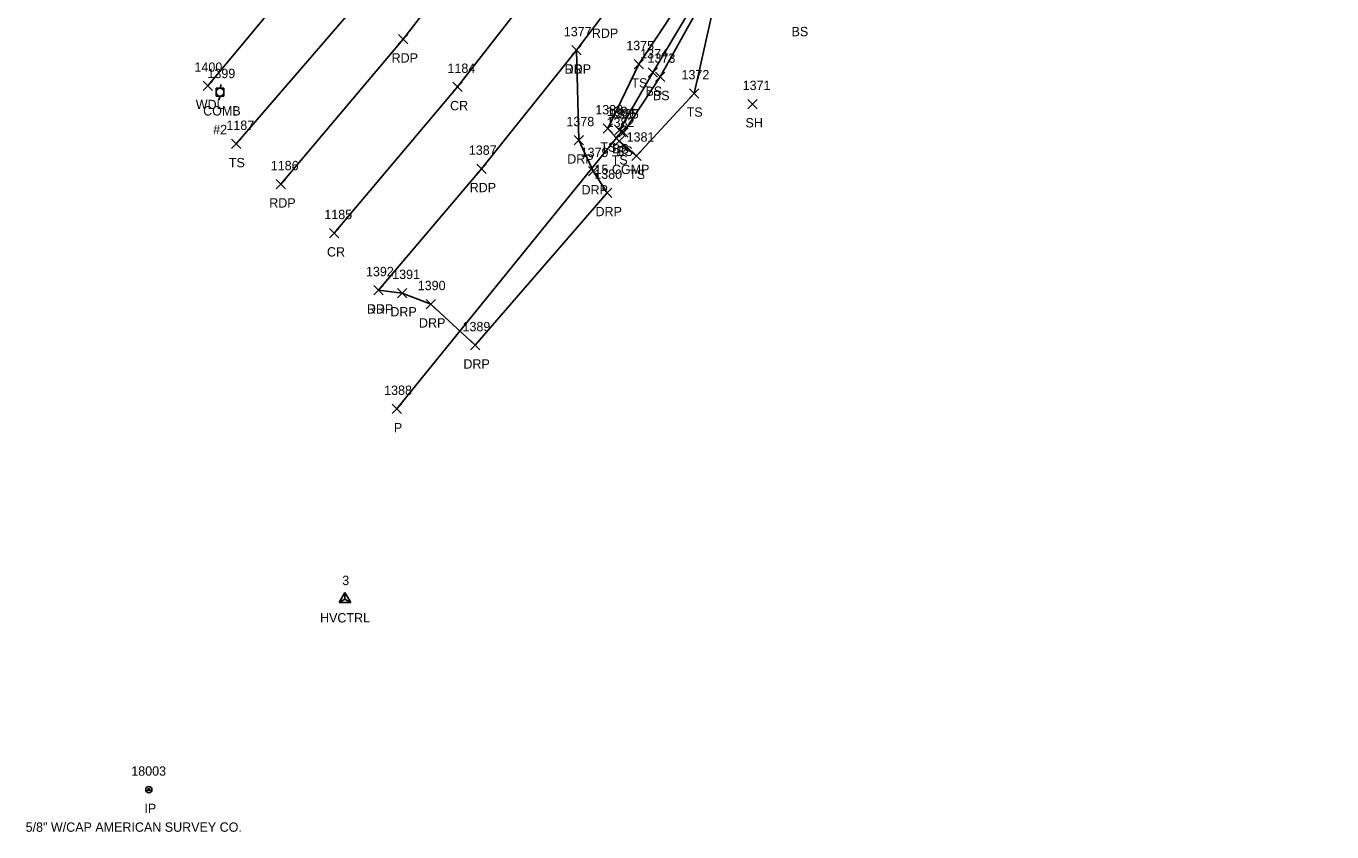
# Model space of a CAD drawing. Extents: x 1599840 to 1601211, y 518904 to 521989.
# Drawn here: x 1600676.4 to 1600955.8, y 521015.9 to 521188.3 of the extents above; entities that cross this region are included whole.
import ezdxf

# ---------------------------------------------------------------- set-up
doc = ezdxf.new("R2010")
doc.units = 0
for name, color, linetype in [('C_A', 7, 'Continuous'), ('C_I', 7, 'Continuous'), ('CPSM', 7, 'Continuous'), ('D_A', 7, 'Continuous'), ('D_C', 7, 'Continuous'), ('D_I', 7, 'Continuous'), ('D_TIC', 7, 'Continuous'), ('DCP', 7, 'Continuous'), ('L_A', 7, 'Continuous'), ('L_I', 7, 'Continuous'), ('L_TIC', 7, 'Continuous'), ('LAWA', 7, 'Continuous'), ('LELB', 7, 'Continuous'), ('M_A', 7, 'Continuous'), ('M_C', 7, 'Continuous'), ('M_I', 7, 'Continuous'), ('MPIR', 7, 'Continuous'), ('P_A', 7, 'Continuous'), ('P_I', 7, 'Continuous'), ('P_TIC', 7, 'Continuous'), ('PET', 7, 'Continuous'), ('PRC', 7, 'Continuous'), ('R_A', 7, 'Continuous'), ('R_I', 7, 'Continuous'), ('R_TIC', 7, 'Continuous'), ('RDP', 7, 'Continuous'), ('U_A', 7, 'Continuous'), ('U_C', 7, 'Continuous'), ('U_I', 7, 'Continuous'), ('UP', 7, 'Continuous')]:
    doc.layers.add(name, color=color, linetype=linetype)

msp = doc.modelspace()

# ---------------------------------------------------------------- linework, layer by layer
at = {"layer": 'CPSM'}
for p, q in [((1600743.33, 521064.98), (1600744.58, 521067.14)), ((1600743.33, 521064.98), (1600744.58, 521065.7)), ((1600745.83, 521064.98), (1600744.58, 521067.14)), ((1600744.58, 521065.7), (1600744.58, 521067.14)), ((1600744.58, 521065.7), (1600744.58, 521065.7)), ((1600744.58, 521065.7), (1600745.83, 521064.98)), ((1600743.33, 521064.98), (1600745.83, 521064.98))]:
    msp.add_line(p, q, dxfattribs=at)
at = {"layer": 'D_TIC'}
for points in [[(1600802.71, 521164.67), (1600804.71, 521166.67)], [(1600804.71, 521164.67), (1600802.71, 521166.67)], [(1600754.68, 521105.4), (1600756.68, 521107.4)], [(1600756.68, 521105.4), (1600754.68, 521107.4)]]:
    msp.add_lwpolyline(points, dxfattribs=at)
at = {"layer": 'DCP'}
msp.add_lwpolyline([(1600803.71, 521165.67), (1600755.68, 521106.4)], dxfattribs=at)
at = {"layer": 'L_TIC'}
for points in [[(1600806.49, 521179.18), (1600808.49, 521181.18)], [(1600808.49, 521179.18), (1600806.49, 521181.18)], [(1600809.47, 521177.41), (1600811.47, 521179.41)], [(1600811.47, 521177.41), (1600809.47, 521179.41)], [(1600811.05, 521176.48), (1600813.05, 521178.48)], [(1600813.05, 521176.48), (1600811.05, 521178.48)], [(1600714.26, 521174.56), (1600716.26, 521176.56)], [(1600716.26, 521174.56), (1600714.26, 521176.56)], [(1600818.31, 521172.94), (1600820.31, 521174.94)], [(1600820.31, 521172.94), (1600818.31, 521174.94)], [(1600830.82, 521170.65), (1600832.82, 521172.65)], [(1600832.82, 521170.65), (1600830.82, 521172.65)], [(1600799.87, 521165.44), (1600801.87, 521167.44)], [(1600801.87, 521165.44), (1600799.87, 521167.44)], [(1600799.87, 521165.44), (1600801.87, 521167.44)], [(1600801.87, 521165.44), (1600799.87, 521167.44)], [(1600802.33, 521165.07), (1600804.33, 521167.07)], [(1600804.33, 521165.07), (1600802.33, 521167.07)], [(1600803.2, 521164.56), (1600805.2, 521166.56)], [(1600805.2, 521164.56), (1600803.2, 521166.56)], [(1600803.2, 521164.56), (1600805.2, 521166.56)], [(1600805.2, 521164.56), (1600803.2, 521166.56)], [(1600720.35, 521162.12), (1600722.35, 521164.12)], [(1600722.35, 521162.12), (1600720.35, 521164.12)], [(1600802.28, 521162.71), (1600804.28, 521164.71)], [(1600804.28, 521162.71), (1600802.28, 521164.71)], [(1600806, 521159.6), (1600808, 521161.6)], [(1600808, 521159.6), (1600806, 521161.6)]]:
    msp.add_lwpolyline(points, dxfattribs=at)
at = {"layer": 'LAWA'}
msp.add_lwpolyline([(1600715.26, 521175.56), (1600743.61, 521209.67), (1600755.16, 521229.87), (1600759.58, 521247.63)], dxfattribs=at)
at = {"layer": 'LELB'}
for points in [[(1600833.08, 521322.84), (1600827.14, 521306.56), (1600810.92, 521276.32), (1600800.69, 521262.52), (1600794.58, 521254.04), (1600785.73, 521239.52), (1600767.25, 521213.82), (1600747.49, 521193.49), (1600721.35, 521163.12)], [(1600856.57, 521262.56), (1600841.46, 521241.68), (1600830.35, 521222.88), (1600827.01, 521208.86), (1600821.28, 521196.5), (1600810.47, 521178.41), (1600803.33, 521166.07), (1600804.2, 521165.56)], [(1600828.05, 521208.69), (1600822.34, 521195.97), (1600812.05, 521177.48), (1600804.2, 521165.56)], [(1600819.4, 521198.14), (1600807.49, 521180.18), (1600800.87, 521166.44)], [(1600824.04, 521195.05), (1600819.31, 521173.94), (1600807, 521160.6), (1600803.28, 521163.71), (1600800.87, 521166.44)]]:
    msp.add_lwpolyline(points, dxfattribs=at)
at = {"layer": 'MPIR'}
msp.add_lwpolyline([(1600702.63, 521025.25), (1600702.34, 521024.75), (1600702.92, 521024.75)], close=True, dxfattribs=at)
msp.add_circle((1600702.63, 521024.91), 0.667, dxfattribs=at)
at = {"layer": 'P_TIC'}
for points in [[(1600756.09, 521184.54), (1600758.09, 521186.54)], [(1600758.09, 521184.54), (1600756.09, 521186.54)], [(1600793.12, 521182.15), (1600795.12, 521184.15)], [(1600795.12, 521182.15), (1600793.12, 521184.15)], [(1600767.67, 521174.32), (1600769.67, 521176.32)], [(1600769.67, 521174.32), (1600767.67, 521176.32)], [(1600772.8, 521156.79), (1600774.8, 521158.79)], [(1600774.8, 521156.79), (1600772.8, 521158.79)], [(1600729.91, 521153.49), (1600731.91, 521155.49)], [(1600731.91, 521153.49), (1600729.91, 521155.49)], [(1600741.32, 521143.02), (1600743.32, 521145.02)], [(1600743.32, 521143.02), (1600741.32, 521145.02)], [(1600750.79, 521130.81), (1600752.79, 521132.81)], [(1600752.79, 521130.81), (1600750.79, 521132.81)]]:
    msp.add_lwpolyline(points, dxfattribs=at)
at = {"layer": 'PET'}
for points in [[(1600925.83, 521507.52), (1600915.18, 521473.31), (1600903.26, 521440.28), (1600887.48, 521401.44), (1600873.35, 521370.15), (1600860.38, 521343.64), (1600847.93, 521319.69), (1600844.65, 521313.14), (1600836.72, 521299.9), (1600818.79, 521271.51), (1600793.69, 521233.92), (1600774.49, 521208.06), (1600757.09, 521185.54), (1600730.91, 521154.49)], [(1600955.79, 521499.34), (1600943.51, 521460.9), (1600932.49, 521430.95), (1600915.63, 521388.21), (1600902.46, 521359.92), (1600888.21, 521330.27), (1600876.23, 521308.06), (1600874.78, 521305.59), (1600851.3, 521265.61), (1600837.44, 521243.85), (1600825.08, 521225.62), (1600799.95, 521190.82), (1600794.12, 521183.15), (1600773.8, 521157.79), (1600751.79, 521131.81)]]:
    msp.add_lwpolyline(points, dxfattribs=at)
at = {"layer": 'PRC'}
msp.add_lwpolyline([(1600941.11, 521503.3), (1600929.22, 521466.1), (1600917.95, 521435.49), (1600901.05, 521394.76), (1600888.43, 521365.83), (1600873.97, 521336.55), (1600862.78, 521315.41), (1600848.88, 521291.08), (1600831.54, 521262.94), (1600805.42, 521224.44), (1600786.95, 521198.81), (1600768.67, 521175.32), (1600742.32, 521144.02)], dxfattribs=at)
at = {"layer": 'R_TIC'}
for points in [[(1600793.12, 521182.15), (1600795.12, 521184.15)], [(1600795.12, 521182.15), (1600793.12, 521184.15)], [(1600793.68, 521162.91), (1600795.68, 521164.91)], [(1600795.68, 521162.91), (1600793.68, 521164.91)], [(1600796.74, 521156.3), (1600798.74, 521158.3)], [(1600798.74, 521156.3), (1600796.74, 521158.3)], [(1600799.73, 521151.65), (1600801.73, 521153.65)], [(1600801.73, 521151.65), (1600799.73, 521153.65)], [(1600750.79, 521130.81), (1600752.79, 521132.81)], [(1600752.79, 521130.81), (1600750.79, 521132.81)], [(1600755.84, 521130.2), (1600757.84, 521132.2)], [(1600757.84, 521130.2), (1600755.84, 521132.2)], [(1600761.95, 521127.82), (1600763.95, 521129.82)], [(1600763.95, 521127.82), (1600761.95, 521129.82)], [(1600771.46, 521119.03), (1600773.46, 521121.03)], [(1600773.46, 521119.03), (1600771.46, 521121.03)]]:
    msp.add_lwpolyline(points, dxfattribs=at)
at = {"layer": 'RDP'}
msp.add_lwpolyline([(1600794.12, 521183.15), (1600794.68, 521163.91), (1600797.74, 521157.3), (1600800.73, 521152.65), (1600772.46, 521120.03), (1600762.95, 521128.82), (1600756.84, 521131.2), (1600751.79, 521131.81)], dxfattribs=at)
at = {"layer": 'UP'}
for p, q in [((1600717.04, 521173.37), (1600717.04, 521175.04)), ((1600717.04, 521175.04), (1600718.71, 521175.04)), ((1600718.13, 521175.87), (1600717.88, 521175.04)), ((1600717.88, 521174.2), (1600717.88, 521174.2)), ((1600718.71, 521175.04), (1600718.71, 521173.37)), ((1600718.71, 521173.37), (1600717.04, 521173.37)), ((1600717.63, 521172.54), (1600717.88, 521173.37))]:
    msp.add_line(p, q, dxfattribs=at)
msp.add_circle((1600717.88, 521174.2), 0.833, dxfattribs=at)

# ---------------------------------------------------------------- texts
at = {"layer": 'C_A'}
msp.add_text('HVCTRL', height=2, dxfattribs=at).set_placement((1600739.27, 521060.7))
at = {"layer": 'C_I'}
msp.add_text('3', height=2, dxfattribs=at).set_placement((1600744.01, 521068.7))
at = {"layer": 'D_A'}
for p in [(1600803.09, 521160.67), (1600755.06, 521101.4)]:
    msp.add_text('P', height=2, dxfattribs=at).set_placement(p)
at = {"layer": 'D_C'}
msp.add_text('15 CGMP', height=2, dxfattribs=at).set_placement((1600798.01, 521156.67))
at = {"layer": 'D_I'}
for s, p in [('1386', (1600800.97, 521168.67)), ('1388', (1600752.99, 521109.4))]:
    msp.add_text(s, height=2, dxfattribs=at).set_placement(p)
at = {"layer": 'L_A'}
for s, p in [('BS', (1600840.17, 521186.17)), ('TS', (1600805.9, 521175.18)), ('BS', (1600808.91, 521173.41)), ('BS', (1600810.49, 521172.48)), ('WDL', (1600712.68, 521170.56)), ('TS', (1600817.72, 521168.94)), ('SH', (1600830.31, 521166.65)), ('TS', (1600799.28, 521161.44)), ('TS', (1600799.28, 521161.44)), ('BS', (1600801.77, 521161.07)), ('TS', (1600801.69, 521158.71)), ('BS', (1600802.64, 521160.56)), ('BS', (1600802.64, 521160.56)), ('TS', (1600719.76, 521158.12)), ('TS', (1600805.4, 521155.6))]:
    msp.add_text(s, height=2, dxfattribs=at).set_placement(p)
at = {"layer": 'L_I'}
for s, p in [('1375', (1600804.8, 521183.18)), ('1374', (1600807.78, 521181.41)), ('1400', (1600712.4, 521178.56)), ('1373', (1600809.35, 521180.48)), ('1372', (1600816.62, 521176.94)), ('1371', (1600829.7, 521174.65)), ('1383', (1600798.17, 521169.44)), ('1383', (1600798.17, 521169.44)), ('1382', (1600800.59, 521166.71)), ('1384', (1600800.63, 521169.07)), ('1385', (1600801.51, 521168.56)), ('1385', (1600801.51, 521168.56)), ('1187', (1600719.23, 521166.12)), ('1381', (1600804.87, 521163.6))]:
    msp.add_text(s, height=2, dxfattribs=at).set_placement(p)
at = {"layer": 'M_A'}
msp.add_text('IP', height=2, dxfattribs=at).set_placement((1600701.68, 521019.91))
at = {"layer": 'M_C'}
msp.add_text('5/8" W/CAP AMERICAN SURVEY CO.', height=2, dxfattribs=at).set_placement((1600676.27, 521015.91))
at = {"layer": 'M_I'}
msp.add_text('18003', height=2, dxfattribs=at).set_placement((1600698.88, 521027.91))
at = {"layer": 'P_A'}
for s, p in [('RDP', (1600797.43, 521185.82)), ('RDP', (1600754.58, 521180.54)), ('RDP', (1600791.61, 521178.15)), ('CR', (1600767.1, 521170.32)), ('RDP', (1600771.29, 521152.79)), ('RDP', (1600728.4, 521149.49)), ('CR', (1600740.75, 521139.02)), ('RDP', (1600749.28, 521126.81))]:
    msp.add_text(s, height=2, dxfattribs=at).set_placement(p)
at = {"layer": 'P_I'}
for s, p in [('1377', (1600791.43, 521186.15)), ('1184', (1600766.54, 521178.32)), ('1387', (1600771.11, 521160.79)), ('1186', (1600728.73, 521157.49)), ('1185', (1600740.19, 521147.02)), ('1392', (1600749.1, 521134.81))]:
    msp.add_text(s, height=2, dxfattribs=at).set_placement(p)
at = {"layer": 'R_A'}
for p in [(1600791.61, 521178.15), (1600792.17, 521158.91), (1600795.23, 521152.3), (1600798.22, 521147.65), (1600749.28, 521126.81), (1600754.32, 521126.2), (1600760.44, 521123.82), (1600769.95, 521115.03)]:
    msp.add_text('DRP', height=2, dxfattribs=at).set_placement(p)
at = {"layer": 'R_I'}
for s, p in [('1377', (1600791.43, 521186.15)), ('1378', (1600791.99, 521166.91)), ('1379', (1600795.04, 521160.3)), ('1380', (1600797.95, 521155.65)), ('1392', (1600749.1, 521134.81)), ('1391', (1600754.71, 521134.2)), ('1390', (1600760.18, 521131.82)), ('1389', (1600769.76, 521123.03))]:
    msp.add_text(s, height=2, dxfattribs=at).set_placement(p)
at = {"layer": 'U_A'}
msp.add_text('COMB', height=2, dxfattribs=at).set_placement((1600714.26, 521169.2))
at = {"layer": 'U_C'}
msp.add_text('#2', height=2, dxfattribs=at).set_placement((1600716.41, 521165.2))
at = {"layer": 'U_I'}
msp.add_text('1399', height=2, dxfattribs=at).set_placement((1600715.18, 521177.2))

doc.saveas('drawing.dxf')
